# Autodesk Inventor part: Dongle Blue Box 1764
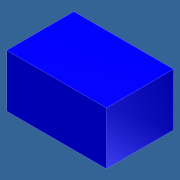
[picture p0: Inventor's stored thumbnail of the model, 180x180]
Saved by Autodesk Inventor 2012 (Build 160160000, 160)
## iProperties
Created: 2010-01
Part Number: Dongle Blue Box 1764
Document SubType Name: Modeling
Designer: jgehrig
Density: 1 g/cm^3
Material: Default
Author: jgehrig
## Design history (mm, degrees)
sketch "Sketch1"
  geometry: L1 (-17.846, -0.772)-(-4.638, -0.772); L2 (-4.638, -0.772)-(-4.638, -7.757); L3 (-4.638, -7.757)-(-17.846, -7.757); L4 (-17.846, -7.757)-(-17.846, -0.772); 1 further point
  constraints: 8 end point, 2 parallel, 1 horizontal, 1 perpendicular
  dimensions: "d0" = 6.985 distance of L3.end L1.start; "d1" = 13.208 distance of L2.end L3.end
extrude "Extrusion1" new body sketch "Sketch1" distance "d2" = 8.89; taper "d3" = 0 deg
body "Solid1"
